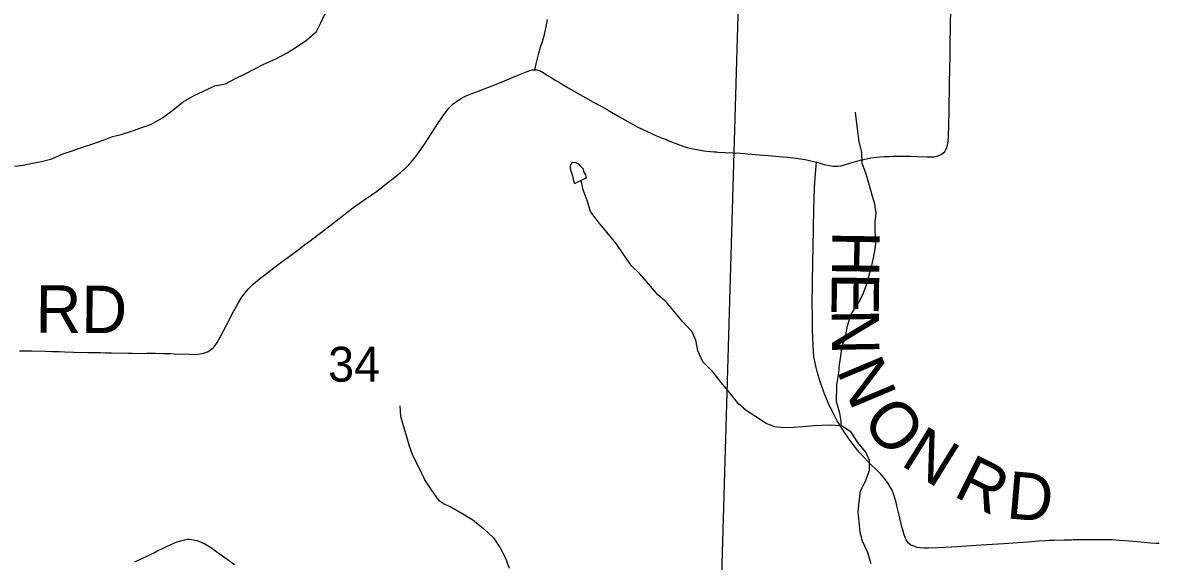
# Model space of a CAD drawing. Extents: x 0 to 34, y 0 to 22.
# Drawn here: x 24.166 to 25.529, y 14.948 to 15.594 of the extents above; entities that cross this region are included whole.
import ezdxf

# ---------------------------------------------------------------- set-up
doc = ezdxf.new("R2010")
doc.units = 0
for name, color, linetype in [('GM_X_Corporation', 7, 'Continuous'), ('GM_X_County_Road', 7, 'Continuous'), ('GM_X_County_Road_Text', 7, 'Continuous'), ('GM_X_Minor_Lake', 7, 'Continuous'), ('GM_X_Minor_River', 7, 'Continuous'), ('GM_X_Section_Text', 7, 'Continuous'), ('GM_X_Township_Road', 7, 'Continuous'), ('GM_X_Township_Road_Text', 7, 'Continuous')]:
    doc.layers.add(name, color=color, linetype=linetype)

msp = doc.modelspace()

# ---------------------------------------------------------------- linework, layer by layer
at = {"layer": 'GM_X_Corporation'}
msp.add_lwpolyline([(23.9985, 15.7225), (25.0261, 15.6992), (24.9959, 14.6707), (24.0266, 14.7005), (23.9793, 14.7018)], close=True, dxfattribs=at)
at = {"layer": 'GM_X_County_Road'}
for points in [[(25.1177, 15.4269), (25.122, 15.4254), (25.1268, 15.4241), (25.1328, 15.4227), (25.1371, 15.4221), (25.1402, 15.4219), (25.1433, 15.422), (25.147, 15.4225), (25.1512, 15.4235), (25.1577, 15.4255), (25.166, 15.4281), (25.172, 15.4296), (25.1774, 15.4308), (25.1829, 15.4318), (25.1896, 15.4327), (25.1983, 15.4334), (25.2045, 15.4337), (25.2094, 15.4338), (25.2169, 15.4339), (25.2305, 15.4338), (25.238, 15.4336), (25.2498, 15.4331), (25.2548, 15.433), (25.2585, 15.4333), (25.2621, 15.4339), (25.265, 15.435), (25.2672, 15.4361), (25.2692, 15.4375), (25.2714, 15.4397), (25.2727, 15.4418), (25.2737, 15.4441), (25.2748, 15.4476), (25.2755, 15.4519), (25.2758, 15.4575), (25.2762, 15.4712), (25.2765, 15.4879), (25.2771, 15.5221), (25.2778, 15.5538), (25.278, 15.5656), (25.2783, 15.5923), (25.2786, 15.6084)], [(24.1618, 15.2006), (24.1767, 15.2004), (24.1922, 15.2001), (24.2014, 15.1998), (24.2095, 15.1996), (24.2163, 15.1994), (24.2269, 15.199), (24.2436, 15.1985), (24.2591, 15.1984), (24.2647, 15.1983), (24.2721, 15.1982), (24.2918, 15.1977), (24.2973, 15.1976), (24.3035, 15.1975), (24.3145, 15.1976), (24.3244, 15.1977), (24.3336, 15.1975), (24.341, 15.1973), (24.3435, 15.1972), (24.3472, 15.1971), (24.3651, 15.1964), (24.3731, 15.1963), (24.3781, 15.1968), (24.3811, 15.1973), (24.3852, 15.1986), (24.388, 15.1999), (24.3906, 15.2015), (24.3944, 15.2047), (24.3964, 15.2071), (24.399, 15.2106), (24.4027, 15.217), (24.4059, 15.2231), (24.4104, 15.232), (24.4182, 15.2469), (24.4242, 15.2577), (24.4277, 15.2636), (24.432, 15.2697), (24.4368, 15.2753), (24.4422, 15.2805), (24.4479, 15.2853), (24.4562, 15.2918), (24.4705, 15.3027), (24.4769, 15.3076), (24.4939, 15.3202), (24.5053, 15.3287), (24.5103, 15.3325), (24.5192, 15.3392), (24.5324, 15.3494), (24.5451, 15.3594), (24.5545, 15.3666), (24.563, 15.3727), (24.5778, 15.383), (24.5838, 15.3873), (24.5898, 15.3917), (24.6017, 15.4007), (24.61, 15.4072), (24.6187, 15.4143), (24.6256, 15.4205), (24.6312, 15.4263), (24.6355, 15.4316), (24.6404, 15.438), (24.6475, 15.4482), (24.6644, 15.4743), (24.6714, 15.4846), (24.6768, 15.4914), (24.6821, 15.4966), (24.6876, 15.5006), (24.6929, 15.5038), (24.6985, 15.5065), (24.7066, 15.5098), (24.7234, 15.5161), (24.7379, 15.5218), (24.7463, 15.5254), (24.7588, 15.5306), (24.7686, 15.5347), (24.7738, 15.5366), (24.7768, 15.5374), (24.7798, 15.5376)], [(24.7798, 15.5376), (24.7817, 15.5376), (24.7841, 15.537), (24.7858, 15.5363), (24.7886, 15.5349), (24.7938, 15.5316), (24.7975, 15.5293), (24.8001, 15.5277), (24.8044, 15.5252), (24.8081, 15.5229), (24.8171, 15.5175), (24.8376, 15.5057), (24.8494, 15.4989), (24.8522, 15.4976), (24.8571, 15.495), (24.8676, 15.489), (24.8804, 15.4816), (24.8912, 15.4755), (24.9027, 15.4693), (24.9144, 15.4634), (24.9258, 15.4585), (24.9298, 15.4568), (24.9326, 15.4556), (24.9372, 15.4538), (24.9407, 15.4524), (24.9534, 15.4475), (24.9574, 15.4461), (24.9627, 15.4445), (24.968, 15.4432), (24.9716, 15.4424), (24.9764, 15.4415), (24.9825, 15.4405), (24.9862, 15.44), (24.9905, 15.4394), (24.9947, 15.4392), (24.9977, 15.439), (24.9989, 15.4389), (25.0174, 15.4379), (25.026, 15.4375), (25.0316, 15.437), (25.0347, 15.4367), (25.0489, 15.4356), (25.065, 15.4345), (25.0687, 15.434), (25.0774, 15.4332), (25.0835, 15.4326), (25.0934, 15.4314), (25.1039, 15.43), (25.1093, 15.4289), (25.1177, 15.4269)], [(24.4197, 14.9439), (24.4108, 14.9505), (24.4002, 14.9581), (24.392, 14.9638), (24.384, 14.9686), (24.3802, 14.9706), (24.375, 14.9726), (24.3727, 14.9733), (24.3666, 14.9742), (24.363, 14.9742), (24.3592, 14.9737), (24.3532, 14.9721), (24.3492, 14.9706), (24.3412, 14.967), (24.3328, 14.963), (24.3278, 14.9606), (24.3244, 14.9589), (24.2998, 14.9471)]]:
    msp.add_lwpolyline(points, dxfattribs=at)
at = {"layer": 'GM_X_Minor_Lake'}
for points in [[(24.8381, 15.4185), (24.8346, 15.4219), (24.8323, 15.4249), (24.8289, 15.426), (24.8247, 15.4264), (24.8232, 15.4245), (24.8217, 15.421), (24.8233, 15.415), (24.8252, 15.4104), (24.8264, 15.4044), (24.8276, 15.4013), (24.8359, 15.4052)], [(24.8359, 15.4052), (24.8397, 15.4071), (24.8419, 15.4083), (24.8411, 15.4117), (24.8388, 15.4155), (24.8381, 15.4185)]]:
    msp.add_lwpolyline(points, dxfattribs=at)
at = {"layer": 'GM_X_Minor_River'}
for points in [[(24.4691, 15.5507), (24.483, 15.558), (24.495, 15.5653), (24.5059, 15.573), (24.5179, 15.5834), (24.5227, 15.5929), (24.5272, 15.6025), (24.5354, 15.6124), (24.5421, 15.6246), (24.5518, 15.6349), (24.5642, 15.6442), (24.5758, 15.6583), (24.5837, 15.669), (24.5888, 15.6819), (24.5932, 15.6937), (24.5973, 15.7033), (24.6017, 15.7162), (24.6084, 15.7295)], [(24.1559, 15.4219), (24.1664, 15.4232), (24.1774, 15.4255), (24.1884, 15.4276), (24.2008, 15.4307), (24.2132, 15.4362), (24.2238, 15.4401), (24.2374, 15.4448), (24.2498, 15.4487), (24.2634, 15.4537), (24.2736, 15.4576), (24.2838, 15.46), (24.2974, 15.4643), (24.3075, 15.4679), (24.3192, 15.4721), (24.3332, 15.4799), (24.3444, 15.4883), (24.3583, 15.4991), (24.3715, 15.5068), (24.3824, 15.5119), (24.3963, 15.5181), (24.4088, 15.5208), (24.4201, 15.5267), (24.4325, 15.5328), (24.4442, 15.5387), (24.4547, 15.5441), (24.4691, 15.5507)], [(25.1473, 15.1106), (25.1473, 15.1163), (25.1457, 15.1257), (25.1414, 15.1394), (25.1421, 15.1599), (25.1442, 15.1743), (25.1453, 15.1838), (25.1467, 15.1941), (25.1485, 15.2062), (25.1526, 15.2199), (25.1548, 15.2306), (25.1589, 15.2439), (25.1675, 15.2572), (25.1731, 15.2679), (25.1776, 15.2797), (25.1809, 15.2911), (25.1835, 15.301), (25.1861, 15.312), (25.1879, 15.323), (25.189, 15.3329), (25.1881, 15.3428), (25.188, 15.3553), (25.1891, 15.3655), (25.1875, 15.3762), (25.1844, 15.3871), (25.1813, 15.3989), (25.177, 15.4125), (25.1724, 15.4254), (25.1719, 15.4386), (25.1688, 15.4511), (25.1672, 15.464), (25.1656, 15.4765), (25.1644, 15.4868)], [(25.183, 14.945), (25.1788, 14.9594), (25.1726, 14.9723), (25.1699, 14.9829), (25.1686, 14.9954), (25.1674, 15.0075), (25.1688, 15.0193), (25.1703, 15.0326), (25.1766, 15.0452), (25.1811, 15.0574), (25.181, 15.0691), (25.1768, 15.0789), (25.1672, 15.0906), (25.1591, 15.1031), (25.1477, 15.1106), (25.1337, 15.1116), (25.1242, 15.1112), (25.114, 15.1107), (25.1007, 15.1095), (25.0901, 15.1086), (25.0787, 15.1081), (25.0677, 15.1096), (25.0571, 15.1133), (25.0445, 15.1219), (25.0331, 15.129), (25.0236, 15.1373), (25.0136, 15.1501), (25.0033, 15.1626), (24.9937, 15.175), (24.9815, 15.1874), (24.9753, 15.2007), (24.973, 15.2135), (24.9684, 15.2234), (24.9573, 15.2354), (24.9473, 15.2475), (24.9374, 15.2592), (24.9275, 15.2678), (24.9164, 15.2806), (24.9057, 15.2927), (24.8958, 15.3025), (24.8866, 15.3157), (24.8774, 15.3293), (24.8663, 15.3428), (24.856, 15.3549), (24.8468, 15.3677), (24.8425, 15.3806), (24.8379, 15.3935), (24.8353, 15.4049)], [(24.6698, 15.0175), (24.6653, 15.0209), (24.6561, 15.0341), (24.648, 15.0461), (24.6406, 15.0612), (24.6337, 15.0751), (24.629, 15.0876), (24.6263, 15.0974), (24.6223, 15.1107), (24.6192, 15.122), (24.6183, 15.1345)], [(24.6698, 15.0175), (24.6791, 15.0135), (24.6916, 15.0064), (24.7054, 14.9981), (24.7183, 14.9876), (24.7302, 14.9763), (24.7382, 14.9642), (24.7447, 14.9521), (24.749, 14.94)]]:
    msp.add_lwpolyline(points, dxfattribs=at)
at = {"layer": 'GM_X_Township_Road'}
for points in [[(24.7798, 15.5376), (24.7815, 15.5447), (24.7833, 15.5525), (24.7847, 15.5573), (24.7867, 15.5645), (24.7889, 15.5715), (24.7913, 15.5799), (24.7933, 15.589), (24.7949, 15.5976)], [(25.5286, 14.9694), (25.5249, 14.9696), (25.5187, 14.97), (25.5021, 14.9714), (25.4922, 14.9724), (25.4804, 14.9733), (25.4767, 14.9735), (25.4724, 14.9738), (25.4662, 14.974), (25.4575, 14.9741), (25.4432, 14.974), (25.4283, 14.9738), (25.4252, 14.9738), (25.4234, 14.9737), (25.4209, 14.9737), (25.419, 14.9737), (25.4166, 14.9736), (25.4147, 14.9736), (25.4023, 14.9732), (25.3961, 14.973), (25.3918, 14.9728), (25.3837, 14.9722), (25.3714, 14.9712), (25.359, 14.9702), (25.3484, 14.9695), (25.3423, 14.9691), (25.3152, 14.9674), (25.2973, 14.9664), (25.2799, 14.9653), (25.2632, 14.9645), (25.252, 14.964), (25.2464, 14.964), (25.2421, 14.9644), (25.2384, 14.9649), (25.2354, 14.9658), (25.2332, 14.9667), (25.2304, 14.9681), (25.2281, 14.9701), (25.2272, 14.971), (25.2252, 14.974), (25.2238, 14.9768), (25.2227, 14.9798), (25.2211, 14.9858), (25.2201, 14.9894), (25.2188, 14.9948), (25.2163, 15.005), (25.214, 15.0147), (25.213, 15.0189), (25.2112, 15.0255), (25.2097, 15.0302), (25.2079, 15.0342), (25.2065, 15.0369), (25.2035, 15.0416), (25.199, 15.0476), (25.1946, 15.0528), (25.1916, 15.056), (25.1799, 15.0672), (25.1738, 15.0734), (25.1689, 15.0789), (25.1627, 15.0867), (25.1568, 15.0947), (25.1485, 15.1071), (25.1425, 15.1168), (25.1391, 15.1231), (25.1331, 15.1348), (25.1285, 15.1458), (25.1259, 15.1522), (25.1217, 15.1647), (25.1189, 15.1741), (25.1168, 15.1821), (25.1155, 15.188), (25.1146, 15.1929), (25.1136, 15.2071), (25.1129, 15.2249), (25.1127, 15.2455), (25.1125, 15.2556), (25.1134, 15.3076), (25.1136, 15.3241), (25.1145, 15.3706), (25.1154, 15.3968), (25.1163, 15.4133), (25.1177, 15.4269)]]:
    msp.add_lwpolyline(points, dxfattribs=at)

# ---------------------------------------------------------------- texts
at = {"layer": 'GM_X_County_Road_Text'}
msp.add_text('RD', height=0.05682, rotation=359.5107, dxfattribs=at).set_placement((24.181, 15.2225))
at = {"layer": 'GM_X_Section_Text'}
msp.add_text('34', height=0.04186, rotation=0, dxfattribs=at).set_placement((24.532, 15.1636))
at = {"layer": 'GM_X_Township_Road_Text'}
for s, rotation, p in [('H', 269.2058, (25.1368, 15.3448)), ('E', 269.2608, (25.1361, 15.2947)), ('N', 271.0346, (25.1355, 15.2503)), ('N', 292.7734, (25.1413, 15.1774)), ('O', 309.7798, (25.1702, 15.1156)), ('N', 328.1517, (25.2171, 15.0642)), ('R', 333.499, (25.2802, 15.027)), ('D', 355.0626, (25.3443, 14.9999))]:
    msp.add_text(s, height=0.0568, rotation=rotation, dxfattribs=at).set_placement(p)

doc.saveas('drawing.dxf')
